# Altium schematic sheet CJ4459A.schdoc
size 127 x 101 mm
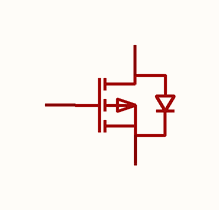
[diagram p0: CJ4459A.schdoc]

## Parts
Q?  cj4459a  [SOT-23-3_L2.9-W1.3-P0.95-LS2.4-BR]  (value not drawn)

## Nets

Not connected (* = marked no-connect by the designer): Q? 1(G) 2(S) 3(D)

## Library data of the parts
Q? = cj4459a: 数量:1个P沟道;漏源电压(Vdss):30V;连续漏极电流(Id):5A;导通电阻(RDS(on)):57mΩ@4.5V;耗散功率(Pd):2W;阈值电压(Vgs(th)):1.6V;; Manufacturer: CJ(江苏长电/长晶); AddInBom: yes; ModelId: c62791f0466c4ae2a892c056b845b0ca; ModelName: SOT-23-3P_L2.9-W1.3-H1.0-LS2.4-P0.95; ModelTransform: 98.425,114.173,0,180,0,0,0.0005,-0.0005,0; Number: 1个P沟道; Drain to Source Voltage: 30V; Current - Continuous Drain(Id): 5A; Pd - Power Dissipation: 2W; Gate Threshold Voltage (Vgs(th)): 1.6V; Gate Charge(Qg): 11.4nC@10V; Input Capacitance(Ciss): 683pF; Reverse Transfer Capacitance (Crss@Vds): 54.6pF; Type: P沟道; Output Capacitance(Coss): 97pF; Vgs: ±20V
